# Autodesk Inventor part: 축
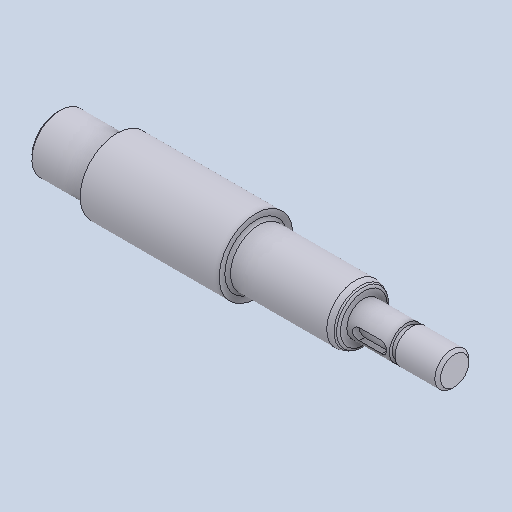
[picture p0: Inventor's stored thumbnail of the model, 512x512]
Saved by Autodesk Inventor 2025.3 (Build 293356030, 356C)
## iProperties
Created: 2025-08
Part Number: 축
Material: 강철, 연강
Document SubType Name: Modeling
Designer: user
Density: 7.86 g/cm^3
Appearance: 기본값
Sending System: Autodesk Inventor 2026
Preprocessor: ST-DEVELOPER v20.1
Author: jhkim
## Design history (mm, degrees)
sketch "스케치1"
  geometry: 1 further point
  constraints: 1 other
feature "솔리드2"
node "솔리드1"
